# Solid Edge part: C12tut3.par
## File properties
Author: CADCIM
Template: ansi part.par
Last saved by: TIET
Revision: 7
Application: Solid Edge
Accuracy: 0.990
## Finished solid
Body 1: solid body, 13 faces, 19 edges, 8 vertices.
  Faces by surface: plane 9, cylinder 4
  Edges by curve: line 10, circle 8, ellipse 1
Bounding box of the edges (mm): 31.750 x 82.544 x 31.750, from (-15.875, -77.8163, -15.875) to (15.875, 4.7283, 15.875).
Cylindrical faces by radius (mm): R5.5944 x1, R6.35 x1, R7.9375 x1, R15.875 x1
Planar faces by outward normal: +x 1, +y 1, +z 1, -x 1, -y 4, oblique 1
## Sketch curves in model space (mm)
line (-22.2359, -0.0325, 12.7) -> (-22.2334, -4.7925, 7.935)
line (-22.2322, -77.8163, 5.5531) -> (-22.2323, -0.0289, 5.77)
line (-22.2262, -77.8103, -5.6356) -> (-22.2263, -0.0229, -5.5751)
line (-22.2326, -68.2917, 6.3138) -> (-22.2326, -77.8167, 6.3087)
line (-22.2326, -77.8167, 6.3087) -> (-22.2258, -77.8099, -6.3913)
line (-22.2258, -68.2849, -6.3862) -> (-22.2258, -77.8099, -6.3913)
line (-22.2376, -0.0342, 15.875) -> (-22.2208, -0.0174, -15.875)
line (-22.2376, 4.7283, 15.8775) -> (-22.2376, -0.0342, 15.875)
line (-22.2376, 4.7283, 15.8775) -> (-22.2208, 4.7451, -15.8725)
line (-22.2208, 4.7451, -15.8725) -> (-22.2208, -0.0174, -15.875)
line (-22.225, -0.0216, -7.9375) -> (-22.225, -68.2841, -7.9737)
line (-22.2334, -0.03, 7.9375) -> (-22.2334, -68.2925, 7.9013)
line (-22.2334, -68.2925, 7.9013) -> (-22.225, -68.2841, -7.9737)
line (0, 0, 22.225) -> (0, 0, -22.225)
line (22.225, 0, 0) -> (-22.225, 0, 0)
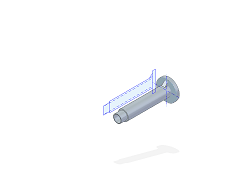
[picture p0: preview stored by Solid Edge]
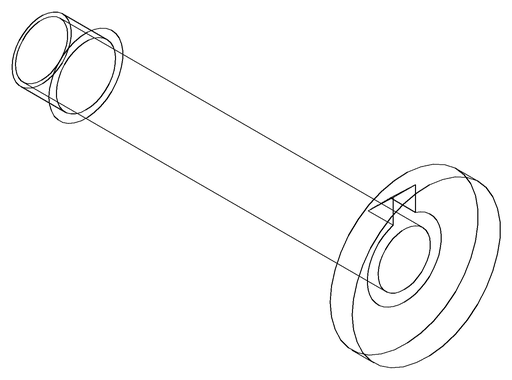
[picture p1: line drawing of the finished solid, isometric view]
